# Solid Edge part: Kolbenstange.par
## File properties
Username: bmolnar
Dokumentum tartalom típus: 0
Author: bmolnar
Last saved by: bmolnar
Revision: 79
Sűrűség: 0,000 kg/m^3
Pontosság: 0,990
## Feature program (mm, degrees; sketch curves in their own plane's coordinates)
base feature "unnamed BaseFeature 1"
sketch for "unnamed Protrusion 1" plane through (90.5, 0, 0) normal (1, 0, 0) x-axis (0, 1, 0)
  circle centre (0, 0) radius 50
extrude "unnamed Protrusion 1" add finite 28 along -normal
thread "unnamed Thread 1"
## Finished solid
Body 1: solid body, 17 faces, 23 edges, 8 vertices.
  Faces by surface: plane 8, cylinder 4, torus 3, cone 2
  Edges by curve: circle 13, line 6, ellipse 2, intersection 2
Bounding box of the edges (mm; curved faces can reach further): 105.500 x 100.000 x 100.000, from (-15, -50, -50) to (90.5, 50, 50).
Cylindrical faces by radius (mm): R7 x1, R8 x1, R12.5 x1, R50 x1
Conical faces (half-angle, radius in mm at the cone's reference point): 20 deg R7.4 x1, 60 deg R7.6 x1
Toroidal faces (ring radius, tube radius in mm): R7.4 r0.4 x2, R10.7 r1.8 x1
Planar faces by outward normal: +x 1, +z 1, -x 3, -z 1, oblique 2
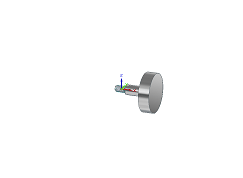
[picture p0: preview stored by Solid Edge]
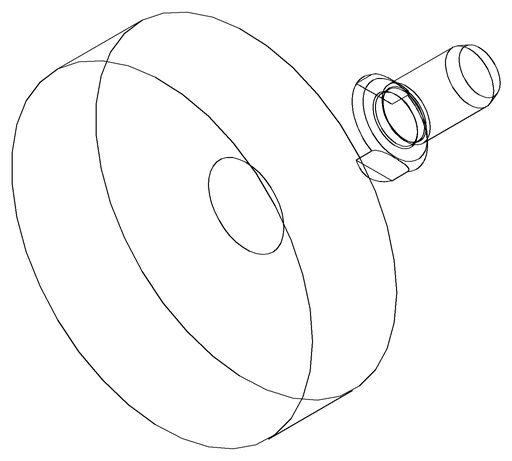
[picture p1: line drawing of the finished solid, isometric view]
